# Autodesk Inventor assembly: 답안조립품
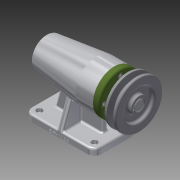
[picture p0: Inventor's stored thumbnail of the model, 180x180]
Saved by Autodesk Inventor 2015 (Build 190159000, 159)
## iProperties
Created: 2018-09
Part Number: 답안조립품
Document SubType Name: Assembly
Designer: line
Author: line
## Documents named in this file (12)
- C:\Users\line\Desktop\김현석 480907V1015\답안조립품.iam
- C:\Users\line\Desktop\김현석 480907V1015\본체.ipt
- C:\Users\line\Desktop\김현석 480907V1015\축.ipt
- C:\Users\line\Desktop\김현석 480907V1015\베어링 6004.ipt
- C:\Users\line\Desktop\김현석 480907V1015\어댑터슬리브.ipt
- C:\Users\line\Desktop\김현석 480907V1015\볼트 M4.ipt
- C:\Users\line\Desktop\김현석 480907V1015\베어링 51202.ipt
- C:\Users\line\Desktop\김현석 480907V1015\커버.ipt
- C:\Users\line\Desktop\김현석 480907V1015\오일 실.ipt
- C:\Users\line\Desktop\김현석 480907V1015\키 5 x 5 x 16.ipt
- C:\Users\line\Desktop\김현석 480907V1015\V벨트풀리.ipt
- C:\Users\line\Desktop\김현석 480907V1015\멈춤나사 M3.ipt
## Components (1 placed, 1 different names)
1. V벨트풀리:1
